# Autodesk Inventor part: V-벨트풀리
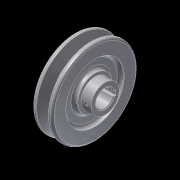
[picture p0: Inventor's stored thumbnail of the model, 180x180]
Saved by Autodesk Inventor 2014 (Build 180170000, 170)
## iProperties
Company: 한국ATC센터
Created: 2014-07
Part Number: V-벨트풀리
Document SubType Name: Modeling
Designer: KYOUNG IL JANG
Density: 2.71 g/cm^3
Material: 알루미늄 6061
Mass: 204.461 g
Surface Area: 234.121 cm^2
Volume: 75.4468 cm^3
Appearance: 알루미늄 - 평지
Author: KYOUNG IL JANG
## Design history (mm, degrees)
sketch "스케치1"
  geometry: L1 (-15, 0)-(15, 0); L2 (-15, 0)-(-15, 17); L3 (-15, 17)-(-11, 17); L4 (-11, 17)-(-11, 29); L5 (-11, 29)-(-15, 29); L6 (-15, 29)-(-15, 42.5); L7 (-15, 42.5)-(-10.976, 42.5); L8 (-10.976, 42.5)-(-7.154, 30); L9 (-7.154, 30)-(-2.846, 30); L10 (-2.846, 30)-(0.976, 42.5); L11 (0.976, 42.5)-(5, 42.5); L12 (5, 42.5)-(5, 29); L13 (5, 29)-(1, 29); L14 (1, 29)-(1, 17); L15 (1, 17)-(5, 17); L16 (5, 17)-(5, 14); L17 (5, 14)-(15, 14); L18 (15, 14)-(15, 0); L19 (-9.6, 38)-(-0.4, 38); 2 further points
  constraints: 38 end point, 11 parallel, 7 collinear, 3 equal length, 3 perpendicular, 2 point on line, 1 coincident, 1 horizontal, 1 midpoint
  dimensions: "d0" = 30 distance of L1.start L1.end; "d1" = 4.5 distance between parallel lines of L7 L19; "d2" = 8 distance between parallel lines of L9 L19; "d3" = 9.2 distance of L19.start L19.end; "d4" = 34 deg angle of L10 L8; "d5" = 20 distance between parallel lines of L12 L6; "d6" = 76 diameter of L19 L1; "d7" = 4 distance of L2.end L3.end; "d8" = 34 diameter of L3 L1; "d9" = 58 diameter of L5 L1; "d10" = 28 diameter of L17 L1
revolve "회전1" sketch "스케치1" stored, may be unused: angle "d11" = 90 deg
sketch "스케치2"
  geometry: L1 (-2.5, 8.124)-(-2.5, 10.8); L2 (-2.5, 10.8)-(2.5, 10.8); L3 (2.5, 10.8)-(2.5, 8.124); A1 r 8.5 centre (0, 0) between (-2.5, 8.124) and (2.5, 8.124); 1 further point
  constraints: 6 end point, 2 parallel, 2 point on circle, 1 centre point, 1 coincident, 1 horizontal, 1 vertical
  dimensions: "d12" = 17 diameter of A1; "d13" = 5 distance of L1.end L2.end; "d14" = 19.3 dimension on A1 L2 (computed from d12)
extrude "돌출1" cut sketch "스케치2" stored distance "d15" = 10; taper "d16" = 0 deg
chamfer "모따기1" distance "d17" = 1; stored, may be unused: second distance "d18" = 2, angle "d19" = 45 deg
node "작업 평면1"
sketch "스케치3"
  geometry: L1 (5, -14)-(5, 14) reference; 3 further points
  constraints: 1 horizontal alignment, 1 midpoint
  dimensions: "d20" = 5 distance from line of L1 point (0, 0)
hole "구멍1" sketch "스케치3" at (0, 0) diameter "d21" = 3.242; stored, may be unused: countersink angle "d25" = 90 deg, drill point angle "d27" = 118 deg; dims "d22" = 6, "d23" = 4, "d24" = 2, "d26" = 8
fillet "모깎기1" dims "d28" = 3, "d29" = 2, "d30" = 0.5, "d31" = 1
node "솔리드1"
